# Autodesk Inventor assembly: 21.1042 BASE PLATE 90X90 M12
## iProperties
Created: 2007-03
Part Number: 21.1042 BASE PLATE 90X90 M12
Document SubType Name: Assembly
Designer: Andy Moles
Author: Andy Moles
